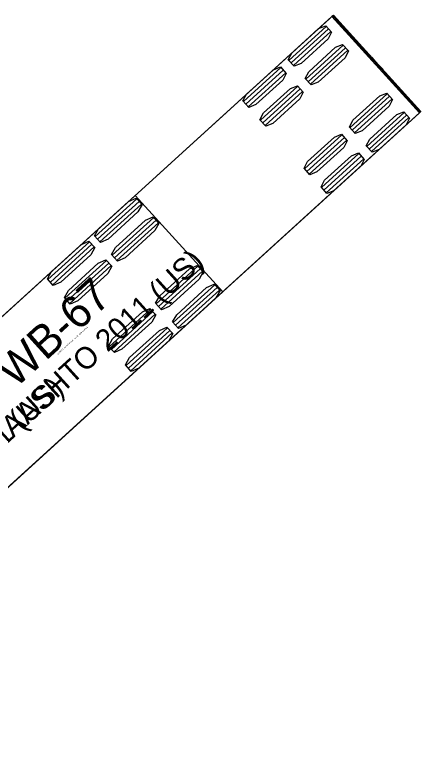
# Model space of a CAD drawing. Extents: x 1639988 to 1641860, y 841974 to 844187.
# Drawn here: x 1640795.46 to 1640821.99, y 844100.65 to 844149.72 of the extents above; entities that cross this region are included whole.
import ezdxf

# ---------------------------------------------------------------- set-up
doc = ezdxf.new("R2010")
doc.units = 0
for name, color, linetype in [('Scratch_Level_1', 7, 'Continuous'), ('Scratch_Level_2', 7, 'Continuous'), ('Scratch_Level_3', 7, 'Continuous')]:
    doc.layers.add(name, color=color, linetype=linetype)

msp = doc.modelspace()

# ---------------------------------------------------------------- linework, layer by layer
at = {"layer": 'Scratch_Level_1'}
for p, q in [((1640803.317, 844137.956), (1640771.858, 844109.38)), ((1640800.695, 844135.265), (1640803.409, 844137.73)), ((1640800.849, 844135.095), (1640803.563, 844137.56)), ((1640809.032, 844131.664), (1640803.317, 844137.956)), ((1640801.003, 844134.925), (1640803.717, 844137.391)), ((1640801.804, 844134.043), (1640804.518, 844136.509)), ((1640801.958, 844133.874), (1640804.673, 844136.339)), ((1640802.113, 844133.704), (1640804.827, 844136.17)), ((1640797.611, 844132.463), (1640800.325, 844134.929)), ((1640797.765, 844132.294), (1640800.479, 844134.759)), ((1640797.919, 844132.124), (1640800.633, 844134.589)), ((1640798.72, 844131.242), (1640801.434, 844133.707)), ((1640798.874, 844131.072), (1640801.588, 844133.538)), ((1640799.028, 844130.903), (1640801.742, 844133.368)), ((1640804.684, 844130.873), (1640807.398, 844133.338)), ((1640804.838, 844130.703), (1640807.553, 844133.169)), ((1640804.993, 844130.534), (1640807.707, 844132.999)), ((1640805.794, 844129.651), (1640808.508, 844132.117)), ((1640777.573, 844103.088), (1640809.032, 844131.664)), ((1640805.948, 844129.482), (1640808.662, 844131.947)), ((1640806.102, 844129.312), (1640808.816, 844131.778)), ((1640801.6, 844128.071), (1640804.314, 844130.537)), ((1640801.754, 844127.902), (1640804.468, 844130.367)), ((1640801.908, 844127.732), (1640804.622, 844130.197)), ((1640802.71, 844126.85), (1640805.424, 844129.315)), ((1640802.864, 844126.68), (1640805.578, 844129.146)), ((1640803.018, 844126.511), (1640805.732, 844128.976))]:
    msp.add_line(p, q, dxfattribs=at)
for points in [[(1640691.488, 844037.554), (1640695.546, 844040.921), (1640699.578, 844044.326), (1640703.587, 844047.766), (1640707.576, 844051.238), (1640711.547, 844054.738), (1640715.504, 844058.262), (1640723.394, 844065.366), (1640803.317, 844137.956), (1640809.032, 844131.664), (1640808.793, 844131.447), (1640808.793, 844131.447)], [(1640808.793, 844131.447), (1640706.365, 844038.416), (1640702.379, 844034.843), (1640698.36, 844031.302), (1640694.302, 844027.802), (1640690.201, 844024.347), (1640686.055, 844020.942), (1640681.863, 844017.59), (1640677.628, 844014.295), (1640673.351, 844011.058), (1640669.032, 844007.881), (1640664.674, 844004.765), (1640660.276, 844001.71), (1640655.842, 843998.712), (1640651.385, 843995.755), (1640642.436, 843989.91), (1640624.5, 843978.327)]]:
    msp.add_lwpolyline(points, dxfattribs=at)
for points in [[(1640801.041, 844134.883), (1640800.657, 844135.307), (1640800.921, 844135.78), (1640802.875, 844137.555), (1640803.371, 844137.772), (1640803.755, 844137.349), (1640803.491, 844136.876), (1640801.537, 844135.101)], [(1640802.151, 844133.662), (1640801.766, 844134.085), (1640802.03, 844134.558), (1640803.984, 844136.333), (1640804.48, 844136.551), (1640804.865, 844136.127), (1640804.601, 844135.655), (1640802.647, 844133.88)], [(1640797.957, 844132.082), (1640797.572, 844132.505), (1640797.837, 844132.978), (1640799.791, 844134.753), (1640800.287, 844134.971), (1640800.671, 844134.547), (1640800.407, 844134.075), (1640798.453, 844132.299)], [(1640799.067, 844130.861), (1640798.682, 844131.284), (1640798.946, 844131.757), (1640800.9, 844133.532), (1640801.396, 844133.749), (1640801.781, 844133.326), (1640801.517, 844132.853), (1640799.562, 844131.078)], [(1640805.031, 844130.491), (1640804.646, 844130.915), (1640804.91, 844131.388), (1640806.864, 844133.163), (1640807.36, 844133.38), (1640807.745, 844132.957), (1640807.481, 844132.484), (1640805.527, 844130.709)], [(1640806.14, 844129.27), (1640805.756, 844129.694), (1640806.02, 844130.166), (1640807.974, 844131.941), (1640808.47, 844132.159), (1640808.854, 844131.736), (1640808.59, 844131.263), (1640806.636, 844129.488)], [(1640801.947, 844127.69), (1640801.562, 844128.113), (1640801.826, 844128.586), (1640803.78, 844130.361), (1640804.276, 844130.579), (1640804.661, 844130.155), (1640804.397, 844129.683), (1640802.442, 844127.908)], [(1640803.056, 844126.469), (1640802.671, 844126.892), (1640802.935, 844127.365), (1640804.89, 844129.14), (1640805.385, 844129.357), (1640805.77, 844128.934), (1640805.506, 844128.461), (1640803.552, 844126.686)]]:
    msp.add_lwpolyline(points, close=True, dxfattribs=at)
at = {"layer": 'Scratch_Level_2'}
for p, q in [((1640816.166, 844149.627), (1640821.881, 844143.336)), ((1640813.353, 844146.762), (1640815.795, 844148.981)), ((1640813.507, 844146.593), (1640815.949, 844148.812)), ((1640813.661, 844146.423), (1640816.103, 844148.642)), ((1640814.462, 844145.541), (1640816.905, 844147.76)), ((1640814.616, 844145.371), (1640817.059, 844147.59)), ((1640814.77, 844145.202), (1640817.213, 844147.421)), ((1640818.718, 844146.922), (1640818.897, 844146.726)), ((1640819.076, 844146.529), (1640819.023, 844146.482)), ((1640819.254, 844146.332), (1640819.433, 844146.136)), ((1640810.392, 844144.073), (1640812.834, 844146.292)), ((1640810.546, 844143.903), (1640812.988, 844146.122)), ((1640810.7, 844143.734), (1640813.143, 844145.952)), ((1640811.501, 844142.852), (1640813.944, 844145.07)), ((1640811.655, 844142.682), (1640814.098, 844144.901)), ((1640811.809, 844142.512), (1640814.252, 844144.731)), ((1640817.342, 844142.37), (1640819.785, 844144.589)), ((1640817.496, 844142.201), (1640819.939, 844144.42)), ((1640817.65, 844142.031), (1640820.093, 844144.25)), ((1640818.451, 844141.149), (1640820.894, 844143.368)), ((1640818.605, 844140.979), (1640821.048, 844143.198)), ((1640818.76, 844140.81), (1640821.202, 844143.029)), ((1640814.381, 844139.681), (1640816.824, 844141.9)), ((1640814.535, 844139.511), (1640816.978, 844141.73)), ((1640814.689, 844139.342), (1640817.132, 844141.561)), ((1640815.491, 844138.46), (1640817.933, 844140.678)), ((1640815.645, 844138.29), (1640818.087, 844140.509)), ((1640815.799, 844138.12), (1640818.241, 844140.339))]:
    msp.add_line(p, q, dxfattribs=at)
for points in [[(1640691.269, 844038.021), (1640695.364, 844041.343), (1640699.43, 844044.698), (1640703.471, 844048.087), (1640707.491, 844051.508), (1640711.492, 844054.959), (1640715.476, 844058.437), (1640719.446, 844061.939), (1640727.354, 844069.003), (1640735.238, 844076.123), (1640816.27, 844149.722), (1640821.986, 844143.431), (1640821.873, 844143.329), (1640821.873, 844143.329)], [(1640816.233, 844149.658), (1640816.219, 844149.674), (1640816.166, 844149.627), (1640811.971, 844145.817), (1640777.039, 844114.086), (1640779.897, 844110.941), (1640782.754, 844107.795), (1640817.686, 844139.525), (1640821.88, 844143.336), (1640821.933, 844143.384), (1640821.918, 844143.4)], [(1640818.951, 844146.771), (1640818.772, 844146.969), (1640818.77, 844146.969), (1640818.719, 844146.922), (1640818.694, 844146.949), (1640816.25, 844149.64), (1640816.249, 844149.641)], [(1640819.25, 844146.337), (1640818.899, 844146.723)], [(1640821.902, 844143.418), (1640821.901, 844143.418), (1640819.457, 844146.109), (1640819.433, 844146.136), (1640819.485, 844146.183), (1640819.484, 844146.184), (1640819.305, 844146.382)], [(1640821.873, 844143.329), (1640711.577, 844043.147), (1640707.605, 844039.571), (1640703.608, 844036.018), (1640699.578, 844032.494), (1640693.5, 844027.235), (1640689.408, 844023.771), (1640685.265, 844020.368), (1640681.075, 844017.026), (1640676.839, 844013.744), (1640672.558, 844010.522), (1640668.235, 844007.361), (1640663.871, 844004.261), (1640659.466, 844001.222), (1640655.021, 843998.244), (1640650.538, 843995.327), (1640648.282, 843993.891), (1640639.353, 843988.021), (1640630.409, 843982.187), (1640612.503, 843970.59)]]:
    msp.add_lwpolyline(points, dxfattribs=at)
for points in [[(1640813.699, 844146.381), (1640813.314, 844146.804), (1640813.54, 844147.243), (1640815.299, 844148.84), (1640815.757, 844149.023), (1640816.142, 844148.6), (1640815.916, 844148.162), (1640814.157, 844146.564)], [(1640814.808, 844145.16), (1640814.424, 844145.583), (1640814.65, 844146.021), (1640816.409, 844147.619), (1640816.866, 844147.802), (1640817.251, 844147.379), (1640817.025, 844146.94), (1640815.266, 844145.343)], [(1640810.738, 844143.692), (1640810.353, 844144.115), (1640810.58, 844144.553), (1640812.338, 844146.151), (1640812.796, 844146.334), (1640813.181, 844145.91), (1640812.955, 844145.472), (1640811.196, 844143.875)], [(1640811.847, 844142.47), (1640811.463, 844142.894), (1640811.689, 844143.332), (1640813.448, 844144.929), (1640813.906, 844145.112), (1640814.29, 844144.689), (1640814.064, 844144.251), (1640812.305, 844142.653)], [(1640817.688, 844141.989), (1640817.304, 844142.413), (1640817.53, 844142.851), (1640819.289, 844144.448), (1640819.746, 844144.631), (1640820.131, 844144.208), (1640819.905, 844143.77), (1640818.146, 844142.172)], [(1640818.798, 844140.768), (1640818.413, 844141.191), (1640818.639, 844141.629), (1640820.398, 844143.227), (1640820.856, 844143.41), (1640821.24, 844142.987), (1640821.014, 844142.548), (1640819.256, 844140.951)], [(1640814.727, 844139.3), (1640814.343, 844139.723), (1640814.569, 844140.161), (1640816.328, 844141.759), (1640816.786, 844141.942), (1640817.17, 844141.518), (1640816.944, 844141.08), (1640815.185, 844139.483)], [(1640815.837, 844138.078), (1640815.452, 844138.502), (1640815.678, 844138.94), (1640817.437, 844140.537), (1640817.895, 844140.72), (1640818.28, 844140.297), (1640818.054, 844139.859), (1640816.295, 844138.261)]]:
    msp.add_lwpolyline(points, close=True, dxfattribs=at)
for centre in [(1640816.266, 844149.672), (1640821.935, 844143.431)]:
    msp.add_circle(centre, 0.0266, dxfattribs=at)
for centre, radius, start, end in [((1640817.73, 844151.018), 2.022, 222.2506, 222.9344), ((1640818.925, 844146.748), 0.0354, 46.5421, 218.7276), ((1640818.925, 844146.747), 0.0352, 223.2249, 42.2253), ((1640819.279, 844146.358), 0.0352, 42.2759, 221.2763), ((1640819.279, 844146.358), 0.0353, 225.5868, 43.9364), ((1640821.936, 844143.431), 0.0363, 241.328, 202.4894)]:
    msp.add_arc(centre, radius, start, end, dxfattribs=at)
at = {"layer": 'Scratch_Level_3'}
for p, q in [((1640816.166, 844149.627), (1640821.881, 844143.336)), ((1640813.353, 844146.762), (1640815.795, 844148.981)), ((1640813.507, 844146.593), (1640815.949, 844148.812)), ((1640813.661, 844146.423), (1640816.103, 844148.642)), ((1640814.462, 844145.541), (1640816.905, 844147.76)), ((1640814.616, 844145.371), (1640817.059, 844147.59)), ((1640814.77, 844145.202), (1640817.213, 844147.421)), ((1640818.718, 844146.922), (1640818.897, 844146.726)), ((1640819.076, 844146.529), (1640819.023, 844146.482)), ((1640819.254, 844146.332), (1640819.433, 844146.136)), ((1640810.392, 844144.073), (1640812.834, 844146.292)), ((1640810.546, 844143.903), (1640812.988, 844146.122)), ((1640810.7, 844143.734), (1640813.143, 844145.952)), ((1640811.501, 844142.852), (1640813.944, 844145.07)), ((1640811.655, 844142.682), (1640814.098, 844144.901)), ((1640811.809, 844142.512), (1640814.252, 844144.731)), ((1640817.342, 844142.37), (1640819.785, 844144.589)), ((1640817.496, 844142.201), (1640819.939, 844144.42)), ((1640817.65, 844142.031), (1640820.093, 844144.25)), ((1640818.451, 844141.149), (1640820.894, 844143.368)), ((1640818.605, 844140.979), (1640821.048, 844143.198)), ((1640818.76, 844140.81), (1640821.202, 844143.029)), ((1640814.381, 844139.681), (1640816.824, 844141.9)), ((1640814.535, 844139.511), (1640816.978, 844141.73)), ((1640814.689, 844139.342), (1640817.132, 844141.561)), ((1640815.491, 844138.46), (1640817.933, 844140.678)), ((1640815.645, 844138.29), (1640818.087, 844140.509)), ((1640815.799, 844138.12), (1640818.241, 844140.339))]:
    msp.add_line(p, q, dxfattribs=at)
for points in [[(1640691.269, 844038.021), (1640695.364, 844041.343), (1640699.43, 844044.698), (1640703.471, 844048.087), (1640707.491, 844051.508), (1640711.492, 844054.959), (1640715.476, 844058.437), (1640719.446, 844061.939), (1640727.354, 844069.003), (1640735.238, 844076.123), (1640816.27, 844149.722), (1640821.986, 844143.431), (1640821.879, 844143.334), (1640821.879, 844143.334)], [(1640816.233, 844149.658), (1640816.219, 844149.674), (1640816.166, 844149.627), (1640811.971, 844145.817), (1640777.039, 844114.086), (1640779.897, 844110.941), (1640782.754, 844107.795), (1640817.686, 844139.525), (1640821.88, 844143.336), (1640821.933, 844143.384), (1640821.918, 844143.4)], [(1640818.951, 844146.771), (1640818.772, 844146.969), (1640818.77, 844146.969), (1640818.719, 844146.922), (1640818.694, 844146.949), (1640816.25, 844149.64), (1640816.249, 844149.641)], [(1640819.25, 844146.337), (1640818.899, 844146.723)], [(1640821.902, 844143.418), (1640821.901, 844143.418), (1640819.457, 844146.109), (1640819.433, 844146.136), (1640819.485, 844146.183), (1640819.484, 844146.184), (1640819.305, 844146.382)], [(1640821.879, 844143.334), (1640711.577, 844043.147), (1640707.605, 844039.571), (1640703.608, 844036.018), (1640699.578, 844032.494), (1640693.5, 844027.235), (1640689.408, 844023.771), (1640685.265, 844020.368), (1640681.075, 844017.026), (1640676.839, 844013.744), (1640672.558, 844010.522), (1640668.235, 844007.361), (1640663.871, 844004.261), (1640659.466, 844001.222), (1640655.021, 843998.244), (1640650.538, 843995.327), (1640648.282, 843993.891), (1640639.353, 843988.021), (1640630.409, 843982.187), (1640612.503, 843970.59)]]:
    msp.add_lwpolyline(points, dxfattribs=at)
for points in [[(1640813.699, 844146.381), (1640813.314, 844146.804), (1640813.54, 844147.243), (1640815.299, 844148.84), (1640815.757, 844149.023), (1640816.142, 844148.6), (1640815.916, 844148.162), (1640814.157, 844146.564)], [(1640814.808, 844145.16), (1640814.424, 844145.583), (1640814.65, 844146.021), (1640816.409, 844147.619), (1640816.866, 844147.802), (1640817.251, 844147.379), (1640817.025, 844146.94), (1640815.266, 844145.343)], [(1640810.738, 844143.692), (1640810.353, 844144.115), (1640810.58, 844144.553), (1640812.338, 844146.151), (1640812.796, 844146.334), (1640813.181, 844145.91), (1640812.955, 844145.472), (1640811.196, 844143.875)], [(1640811.847, 844142.47), (1640811.463, 844142.894), (1640811.689, 844143.332), (1640813.448, 844144.929), (1640813.906, 844145.112), (1640814.29, 844144.689), (1640814.064, 844144.251), (1640812.305, 844142.653)], [(1640817.688, 844141.989), (1640817.304, 844142.413), (1640817.53, 844142.851), (1640819.289, 844144.448), (1640819.746, 844144.631), (1640820.131, 844144.208), (1640819.905, 844143.77), (1640818.146, 844142.172)], [(1640818.798, 844140.768), (1640818.413, 844141.191), (1640818.639, 844141.629), (1640820.398, 844143.227), (1640820.856, 844143.41), (1640821.24, 844142.987), (1640821.014, 844142.548), (1640819.256, 844140.951)], [(1640814.727, 844139.3), (1640814.343, 844139.723), (1640814.569, 844140.161), (1640816.328, 844141.759), (1640816.786, 844141.942), (1640817.17, 844141.518), (1640816.944, 844141.08), (1640815.185, 844139.483)], [(1640815.837, 844138.078), (1640815.452, 844138.502), (1640815.678, 844138.94), (1640817.437, 844140.537), (1640817.895, 844140.72), (1640818.28, 844140.297), (1640818.054, 844139.859), (1640816.295, 844138.261)]]:
    msp.add_lwpolyline(points, close=True, dxfattribs=at)
for centre in [(1640816.266, 844149.672), (1640821.935, 844143.431)]:
    msp.add_circle(centre, 0.0266, dxfattribs=at)
for centre, radius, start, end in [((1640817.73, 844151.018), 2.022, 222.2506, 222.9344), ((1640818.925, 844146.748), 0.0354, 46.5421, 218.7276), ((1640818.925, 844146.747), 0.0352, 223.2249, 42.2253), ((1640819.279, 844146.358), 0.0352, 42.2759, 221.2763), ((1640819.279, 844146.358), 0.0353, 225.5868, 43.9364), ((1640821.936, 844143.431), 0.0363, 241.328, 202.4894)]:
    msp.add_arc(centre, radius, start, end, dxfattribs=at)

# ---------------------------------------------------------------- texts
at = {"layer": 'Scratch_Level_1'}
msp.add_text('AASHTO 2001 (US)', height=1.41667, rotation=42.2506, dxfattribs=at).set_placement((1640786.204, 844113.79))
at = {"layer": 'Scratch_Level_2'}
for s, height, p in [('AASHTO 2011 (US)', 1.41667, (1640795.347, 844122.094)), ('WB-67', 2.125, (1640795.466, 844125.312)), ('(c) 2019 Transoft Solutions, Inc. All rights reserved.', 0.085, (1640798.259, 844127.562))]:
    msp.add_text(s, height=height, rotation=42.2506, dxfattribs=at).set_placement(p)
at = {"layer": 'Scratch_Level_3'}
for s, height, p in [('AASHTO 2011 (US)', 1.41667, (1640795.347, 844122.094)), ('WB-67', 2.125, (1640795.466, 844125.312)), ('(c) 2019 Transoft Solutions, Inc. All rights reserved.', 0.085, (1640798.259, 844127.562))]:
    msp.add_text(s, height=height, rotation=42.2506, dxfattribs=at).set_placement(p)

doc.saveas('drawing.dxf')
